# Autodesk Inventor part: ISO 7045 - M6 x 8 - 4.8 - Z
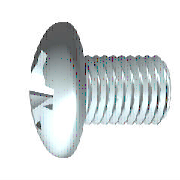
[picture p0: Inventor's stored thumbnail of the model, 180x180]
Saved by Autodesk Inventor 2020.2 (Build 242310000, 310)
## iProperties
Created: 2019-01
Part Number: ISO 7045 - M6 x 8 - 4.8 - Z
Material: Acier
Description: Vis à tête cylindrique à empreinte cruciforme de type Z - Produit de classe A
Document SubType Name: Modeling
Standard: ISO 7045
Designer: Philippe
Standard Revision: Third edition 2011-09-01
Standards Organization: ISO
Language: fr-FR
Size Designation: M6 x 8 - 4.8 - Z
Categories: <MemberInstance><Categories><Category DisplayName="Visserie" InternalName="e4da775c-781d-43d5-af7c-5136215cf5a6" Mnemonic="FSTN"><Category DisplayName="Vis" Int
Density: 7.85 g/cm^3
Appearance: Plaque
IsCustomPart: 0
Author: Philippe
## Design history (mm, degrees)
workplane "Work Plane3"
sketch "Esquisse4"
  geometry: L1 (-9, 0)-(9, 0) reference; L2 (0, -9)-(0, 9) reference; L3 (0, 0)-(6.428, 6.428); L4 (0, 0)-(6.428, -6.428); L5 (0, 0)-(-6.428, 6.428); L6 (0, 0)-(-6.428, -6.428); L7 (2.369, 2.369)-(0, 0.5); L8 (-2.369, 2.369)-(-0.5, 0); L9 (-2.369, -2.369)-(0, -0.5); L10 (2.369, -2.369)-(0.5, 0); L11 (2.369, 2.369)-(0.5, 0); L12 (-2.369, 2.369)-(0, 0.5); L13 (-2.369, -2.369)-(-0.5, 0); L14 (2.369, -2.369)-(0, -0.5); C1 r 5.907 at (0, 0) reference; A1 r 0.5 centre (0, 0) between (0, 0.5) and (-0.5, 0); A2 r 3.35 centre (0, 0) between (2.369, 2.369) and (2.369, -2.369); 1 further point
  constraints: 24 end point, 10 point on line, 7 point on circle, 3 perpendicular, 3 symmetric about line, 2 centre point, 2 coincident, 3 other
  dimensions: "d11" = 1 diameter of A1 (= 0.5 x SBR); "d14" = 45 deg angle of L3 L1; "d35" = 2.36881 distance from line of L1 L7.start (= 0.353553 x SDM)
extrude "Coupe en étoile" cut sketch "Esquisse4" distance "d12" = 4.6 (= KOH); taper "d13" = -10 deg
sketch "Esquisse2"
  geometry: L1 (-8.432, 0)-(9.246, 0) reference; L2 (0, -8.432)-(0, 9.246) reference; L3 (0, 3.35)-(0, 0); L4 (0, 0)-(3.35, 0); L5 (0, 0)-(6.721, 6.721); L6 (1, 3.197)-(0.533, 1.588); L7 (3.197, 1)-(1.588, 0.533); L8 (3.197, -1)-(1.588, -0.533); L9 (1, -3.197)-(0.533, -1.588); L10 (-1, 3.197)-(-0.533, 1.588); L11 (-3.197, 1)-(-1.588, 0.533); L12 (-1, -3.197)-(-0.533, -1.588); L13 (-3.197, -1)-(-1.588, -0.533); C1 r 5.907 at (0, 0) reference; A1 r 1.34 centre (0, 0) between (1.34, 0) and (0, 1.34); A2 r 0.398 centre (0.915, 1.477) between (0.533, 1.588) and (1.196, 1.196); A3 r 0.398 centre (1.477, 0.915) between (1.196, 1.196) and (1.588, 0.533); A4 r 3.35 centre (0, 0) between (3.35, 0) and (3.197, 1); A5 r 3.35 centre (0, 0) between (1, 3.197) and (0, 3.35); A6 r 3.35 centre (0, 0) between (3.197, 1) and (1, 3.197); A7 r 3.35 centre (0, 0) between (0, -3.35) and (1, -3.197); A8 r 3.35 centre (0, 0) between (1, -3.197) and (3.197, -1); A9 r 3.35 centre (0, 0) between (3.197, -1) and (3.35, 0); A10 r 0.398 centre (0.915, -1.477) between (1.196, -1.196) and (0.533, -1.588); A11 r 0.398 centre (1.477, -0.915) between (1.588, -0.533) and (1.196, -1.196); A12 r 0.398 centre (-0.915, 1.477) between (-1.196, 1.196) and (-0.533, 1.588); A13 r 0.398 centre (-1.477, 0.915) between (-1.588, 0.533) and (-1.196, 1.196); A14 r 3.35 centre (0, 0) between (-3.197, 1) and (-3.35, 0); A15 r 3.35 centre (0, 0) between (-1, 3.197) and (-3.197, 1); A16 r 3.35 centre (0, 0) between (0, 3.35) and (-1, 3.197); A17 r 3.35 centre (0, 0) between (-3.35, 0) and (-3.197, -1); A18 r 3.35 centre (0, 0) between (-3.197, -1) and (-1, -3.197); A19 r 3.35 centre (0, 0) between (-1, -3.197) and (0, -3.35); A20 r 0.398 centre (-1.477, -0.915) between (-1.196, -1.196) and (-1.588, -0.533); A21 r 0.398 centre (-0.915, -1.477) between (-0.533, -1.588) and (-1.196, -1.196); A22 r 1.675 centre (0, 0) between (1.675, 0) and (0, 1.675)
  constraints: 46 point on circle, 25 symmetric about line, 22 centre point, 22 end point, 6 tangent, 4 coincident, 3 collinear, 3 point on line, 1 midpoint, 1 perpendicular, 22 other
  dimensions: "d4" = 45 deg angle of L5 L4; "d5" = 2.68 diameter of A1 (= 0.4 x SDM); "d6" = 6.7 diameter of A6 (= SDM); "d7" = 1 distance from line of L6.start L3 (= 0.5 x SBR); "d20" = 3.35 diameter of A22 (= 0.5 x SDM)
extrude "Rainure" join sketch "Esquisse2" taper "d21" = 5 deg; stored distance "d54" = 10
revolve "Coupe" stored, may be unused: angle "d56" = 90 deg
revolve "Corps" stored, may be unused: angle "d18" = 90 deg
workplane "Work Plane1"
body "Solid1"
sketch "Esquisse1"
  geometry: L1 (8, 0)-(8, 3); L2 (8, 3)-(2, 3); L3 (3.962, 5.08)-(3.962, 5.08); L4 (-4.6, 0)-(-4.6, 5.839); L5 (-4.106, 3.104)-(-2.316, 2.211); L6 (-2.316, 2.211)-(-1.14, 0); L7 (-1.14, 0)-(8, 0); L8 (-7.685, 0)-(10.614, 0) reference; L9 (0, -1.212)-(0, 7.273) reference; L10 (-4.106, 3.104)-(-4.6, 3.35); L11 (-2.669, 5.907)-(-4.6, 5.839); L12 (-2.669, 5.907)-(0, 6); L13 (0, 6)-(0, 2.729); L14 (0, 2.729)-(1.387, 2.729); L15 (1.387, 2.729)-(2, 3); L16 (2, 3)-(0, 3); A1 r 10 centre (5.4, 0) between (-2.669, 5.907) and (-4.6, 0)
  constraints: 28 end point, 5 point on line, 4 collinear, 4 point on circle, 3 parallel, 2 perpendicular, 1 centre point, 1 horizontal, 1 tangent
  dimensions: "d1" = 6 diameter of L2 L7 (= GD); "d2" = 3.46 distance from line of L6.end L4 (= STI); "d16" = 6.7 diameter of L10.end L7 (= SDM); "d17" = 62 deg angle of L6 L7; "d19" = 26.5 deg angle of L5 L7; "d23" = 12 diameter of L12.end L7 (= KOD); "d24" = 2 deg angle of L12 L7 (= KEWI); "d25" = 4.6 distance between parallel lines of L4 L13 (= KOH); "d26" = 10 radius of A1 (= KR); "d28" = 5.45873 diameter of L14 L7 (= BDM); "d29" = 6 distance of L1.end L2.end (= GEL); "d30" = 0.61345 horizontal distance of L14.end L2.end (= GAL); "d31" = 8 distance between parallel lines of L13 L1 (= NLG)
fillet "Congé1" dims "d32" = 2 (= RR)
fillet "Congé2" dims "d22" = 0.4 (= 0.2 x SBR)
feature "Filetage" dims "d8" = 6 (= GEL), "d9" = 0
chamfer "Chanfrein1" distance "d36" = 0.61345 (= -0.5 x SPD + 0.5 x GD); stored, may be unused: second distance "d37" = 0.61355 (computed from GUL), angle "d81" = 45 deg
other parameters: "GD" = 6 [user parameter; used in 2 equation terms], "NLG" = 8 [user parameter; used in 1 equation term], "GEL" = 6 [user parameter; used in 2 equation terms], "KOD" = 12 [user parameter; used in 1 equation term], "KOH" = 4.6 [user parameter; used in 3 equation terms], "SDM" = 6.7 [user parameter; used in 5 equation terms], "STI" = 3.46 [user parameter; used in 1 equation term], "SBR" = 2 [user parameter; used in 3 equation terms], "KEWI" = 2 deg [user parameter; used in 1 equation term], "d3" = -4.6 (= -KOH), "d10" = 0, "KR" = 10 [user parameter; used in 1 equation term], "BDM" = 5.45873 [user parameter; used in 1 equation term], "GAL" = 0.61345 (= 0.61345 x PTC) [user parameter; used in 1 equation term], "GUL" = 0.61345 (= 0.61345 x PTC) [user parameter; used in 1 equation term], "RR" = 2 [user parameter; used in 1 equation term], "SPD" = 4.7731 (= NND - 1.2269 x PTC) [user parameter; used in 1 equation term], "d82" = 0, "d83" = 0, "PTC" = 1 [user parameter; used in 5 equation terms], "THREADDIA" = 6 [user parameter; used in 1 equation term], "TOA" = 30 deg [user parameter], "NND" = 6 [user parameter; used in 1 equation term], "GD1" = 4.7731 (= THREADDIA - 1.2269 x PTC) [user parameter]
